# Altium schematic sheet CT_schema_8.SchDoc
size 277 x 170 mm
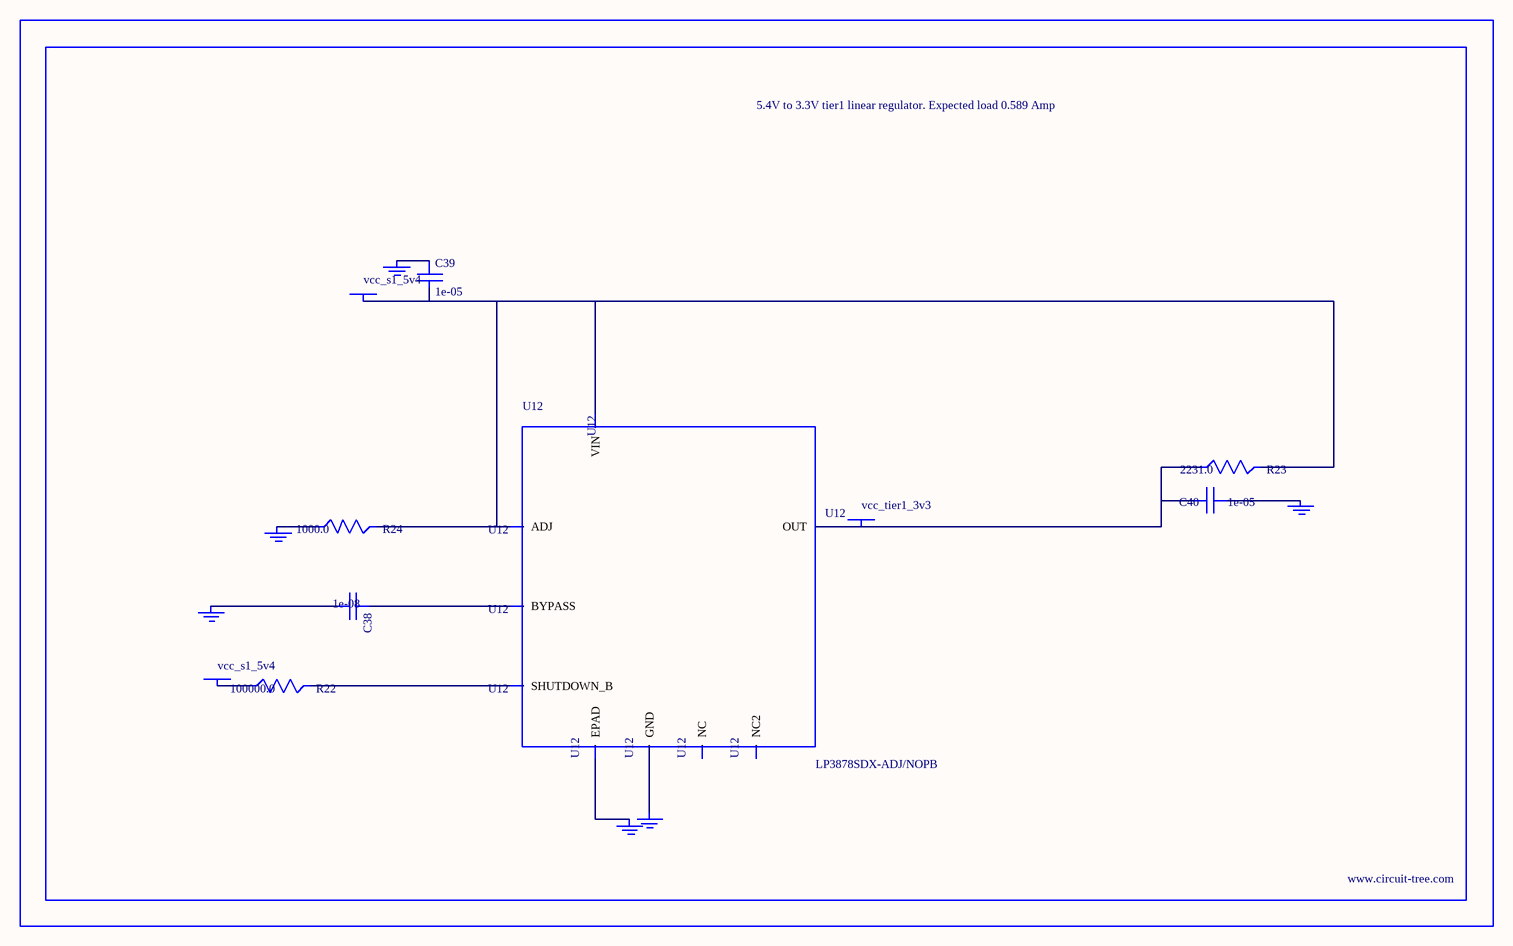
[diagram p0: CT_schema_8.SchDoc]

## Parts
BORDER7  (no value)
C38  1e-08  [C0402]
C39  1e-05  [C1206]
C40  1e-05  [C1210]
GND_INSTANCE_7_0  (no value)
GND_INSTANCE_7_1  (no value)
GND_INSTANCE_7_2  (no value)
GND_INSTANCE_7_3  (no value)
GND_INSTANCE_7_4  (no value)
GND_INSTANCE_7_5  (no value)
POWER_INSTANCE_7_0  vcc_s1_5v4
POWER_INSTANCE_7_1  vcc_s1_5v4
POWER_INSTANCE_7_2  vcc_tier1_3v3
R22  100000.0  [R0603]
R23  2231.0  [R0603]
R24  1000.0  [R0603]
U12  LP3878SDX-ADJ/NOPB  [WSON-8]

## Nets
NetC38_1: C38.1 U12.1(BYPASS)
NetC38_2: C38.2 GND_INSTANCE_7_0.0(GND)
NetC39_1: C39.1 GND_INSTANCE_7_1.0(GND)
NetC39_2: C39.2 POWER_INSTANCE_7_0.0(PWR) R23.2 R24.2 U12.4(VIN) U12.6(ADJ)
NetC40_1: C40.1 GND_INSTANCE_7_2.0(GND)
NetC40_2: C40.2 POWER_INSTANCE_7_2.0(PWR) R23.1 U12.5(OUT)
NetGND_INSTANCE_7_3_0: GND_INSTANCE_7_3.0(GND) R24.1
NetGND_INSTANCE_7_4_0: GND_INSTANCE_7_4.0(GND) U12.PAD(EPAD)
NetGND_INSTANCE_7_5_0: GND_INSTANCE_7_5.0(GND) U12.3(GND)
NetPOWER_INSTANCE_7_1_0: POWER_INSTANCE_7_1.0(PWR) R22.1
NetR22_2: R22.2 U12.8(SHUTDOWN_B)

Not connected (* = marked no-connect by the designer): U12 2(NC) 7(NC2)

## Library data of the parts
BORDER7 = BORDER_PAGE7
C38 = C0402C103K3RAC
C39 = C1206C106K3RACTU
C40 = GRM32DR61E106MA12L
GND_INSTANCE_7_0-GND_INSTANCE_7_5 = GND
POWER_INSTANCE_7_0-POWER_INSTANCE_7_2 = PWR
R22 = RC0603JR-07100KL
R23 = R23
R24 = RC0603JR-071KL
